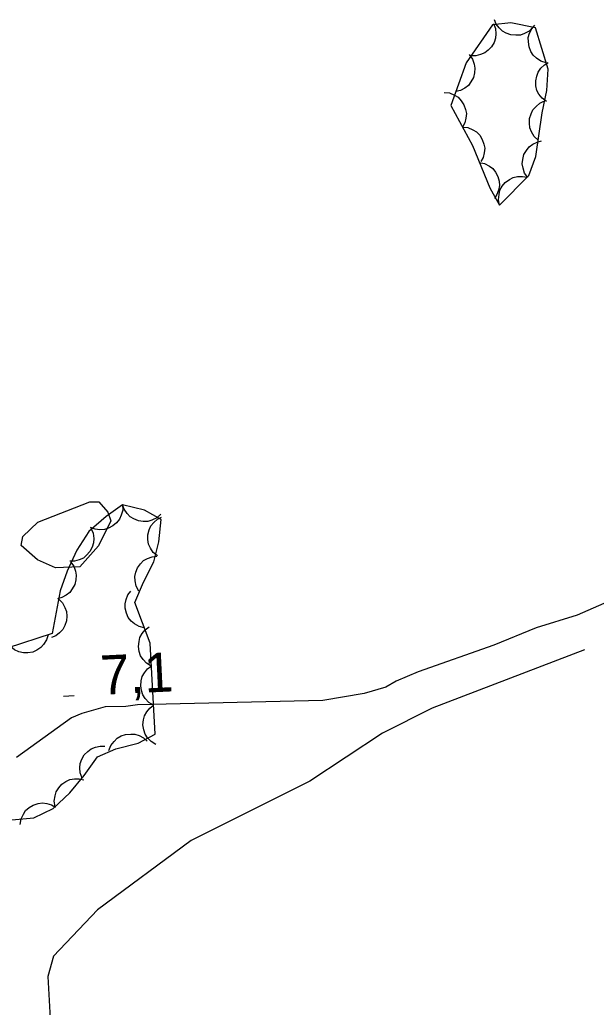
# Model space of a CAD drawing. Extents: x 336540 to 340074, y 5572036 to 5573747.
# Drawn here: x 337314.2 to 337358.4, y 5573040 to 5573115.5 of the extents above; entities that cross this region are included whole.
import ezdxf

# ---------------------------------------------------------------- set-up
doc = ezdxf.new("R2010")
doc.units = 0
for name, color, linetype in [('Niveau 2', 7, 'Continuous'), ('Niveau 3', 7, 'Continuous'), ('Niveau 44', 7, 'Continuous')]:
    doc.layers.add(name, color=color, linetype=linetype)

msp = doc.modelspace()

# ---------------------------------------------------------------- linework, layer by layer
at = {"layer": 'Niveau 2'}
for points in [[(337314.36, 5573075.34), (337314.48, 5573076.02), (337315.62, 5573077.11), (337319.61, 5573078.66), (337320.29, 5573078.68), (337320.99, 5573077.88), (337321.21, 5573077.23), (337320.27, 5573075.31), (337318.84, 5573073.71), (337316.98, 5573073.62), (337315.6, 5573074.23), (337314.36, 5573075.34)], [(337359.35, 5573071.07), (337356.9, 5573070), (337353.76, 5573069.03), (337350.53, 5573067.72), (337344.72, 5573065.67), (337343.04, 5573064.96), (337342.26, 5573064.49), (337340.59, 5573064), (337337.44, 5573063.48), (337323.26, 5573063.15), (337322.36, 5573063.02), (337320.78, 5573062.98), (337318.99, 5573062.49), (337318.21, 5573062.14), (337314, 5573059.11)], [(337357.47, 5573067.35), (337345.81, 5573062.88), (337341.99, 5573060.98), (337336.44, 5573057.31), (337327.35, 5573052.76), (337320.18, 5573047.47), (337316.82, 5573043.91), (337316.39, 5573042.35), (337316.57, 5573039.16), (337315.31, 5573034), (337313.57, 5573031.35)]]:
    msp.add_lwpolyline(points, dxfattribs=at)
at = {"layer": 'Niveau 3'}
msp.add_line((337317.6, 5573063.81), (337318.4, 5573063.85), dxfattribs=at)
at = {"layer": 'Niveau 44'}
for points in [[(337353.51, 5573114.98), (337353.22, 5573114.68), (337352.86, 5573114.49), (337352.55, 5573114.38), (337352.2, 5573114.36), (337351.83, 5573114.4), (337351.47, 5573114.53), (337351.18, 5573114.68), (337350.93, 5573114.92), (337350.71, 5573115.22), (337350.57, 5573115.55)], [(337350.96, 5573101.37), (337353.19, 5573103.64), (337353.74, 5573105.1), (337354.23, 5573108.42), (337354.59, 5573110.13), (337354.67, 5573111.77), (337353.71, 5573114.94), (337351.82, 5573115.31), (337350.41, 5573115.15), (337348.41, 5573112.26), (337347.24, 5573109), (337348.88, 5573105.92), (337350.22, 5573102.7), (337350.96, 5573101.37)], [(337350.49, 5573115.27), (337350.64, 5573114.88), (337350.67, 5573114.47), (337350.66, 5573114.14), (337350.54, 5573113.81), (337350.35, 5573113.49), (337350.09, 5573113.22), (337349.83, 5573113.01), (337349.51, 5573112.88), (337349.15, 5573112.8), (337348.79, 5573112.8)], [(337354.52, 5573112.26), (337354.12, 5573112.38), (337353.79, 5573112.61), (337353.54, 5573112.83), (337353.35, 5573113.13), (337353.22, 5573113.47), (337353.17, 5573113.85), (337353.16, 5573114.18), (337353.26, 5573114.52), (337353.43, 5573114.85), (337353.65, 5573115.13)], [(337348.63, 5573112.88), (337348.88, 5573112.54), (337349.01, 5573112.16), (337349.08, 5573111.84), (337349.05, 5573111.49), (337348.96, 5573111.13), (337348.77, 5573110.79), (337348.58, 5573110.53), (337348.3, 5573110.32), (337347.97, 5573110.15), (337347.62, 5573110.06)], [(337354.55, 5573109.29), (337354.21, 5573109.54), (337353.97, 5573109.86), (337353.82, 5573110.15), (337353.74, 5573110.5), (337353.73, 5573110.87), (337353.81, 5573111.24), (337353.91, 5573111.55), (337354.12, 5573111.84), (337354.39, 5573112.09), (337354.69, 5573112.28)], [(337346.71, 5573109.99), (337347.13, 5573109.95), (337347.5, 5573109.79), (337347.79, 5573109.62), (337348.03, 5573109.36), (337348.23, 5573109.05), (337348.35, 5573108.69), (337348.42, 5573108.37), (337348.38, 5573108.02), (337348.29, 5573107.66), (337348.12, 5573107.34)], [(337353.92, 5573106.34), (337353.62, 5573106.63), (337353.41, 5573106.98), (337353.28, 5573107.28), (337353.24, 5573107.63), (337353.26, 5573108), (337353.38, 5573108.36), (337353.51, 5573108.66), (337353.75, 5573108.92), (337354.04, 5573109.16), (337354.36, 5573109.31)], [(337348.12, 5573107.34), (337348.54, 5573107.3), (337348.91, 5573107.14), (337349.2, 5573106.97), (337349.44, 5573106.71), (337349.64, 5573106.4), (337349.76, 5573106.04), (337349.83, 5573105.72), (337349.79, 5573105.37), (337349.7, 5573105.01), (337349.53, 5573104.7)], [(337353.13, 5573103.47), (337352.88, 5573103.81), (337352.76, 5573104.2), (337352.69, 5573104.52), (337352.73, 5573104.87), (337352.83, 5573105.23), (337353.02, 5573105.56), (337353.22, 5573105.82), (337353.5, 5573106.03), (337353.83, 5573106.19), (337354.18, 5573106.28)], [(337349.41, 5573104.64), (337349.82, 5573104.56), (337350.18, 5573104.36), (337350.45, 5573104.17), (337350.66, 5573103.89), (337350.83, 5573103.56), (337350.92, 5573103.19), (337350.96, 5573102.86), (337350.89, 5573102.52), (337350.76, 5573102.17), (337350.57, 5573101.87)], [(337350.96, 5573101.37), (337350.88, 5573101.78), (337350.92, 5573102.18), (337350.99, 5573102.51), (337351.16, 5573102.81), (337351.4, 5573103.1), (337351.71, 5573103.32), (337351.99, 5573103.48), (337352.34, 5573103.56), (337352.71, 5573103.57), (337353.06, 5573103.51)], [(337311.94, 5573054.2), (337315.33, 5573054.51), (337316.79, 5573055.22), (337318.07, 5573056.41), (337319.16, 5573057.74), (337320.18, 5573059.16), (337321.6, 5573059.77), (337323.31, 5573060.2), (337324.61, 5573060.91), (337324.21, 5573067.85), (337323.05, 5573070.97), (337323.7, 5573072.53), (337324.51, 5573074.09), (337324.89, 5573075.6), (337325.07, 5573077.33), (337323.8, 5573078.03), (337322.1, 5573078.44), (337320.85, 5573077.56), (337319.53, 5573076.4), (337318.61, 5573074.97), (337317.87, 5573073.38), (337317.33, 5573071.86), (337316.72, 5573068.61), (337313.29, 5573067.49)], [(337322.11, 5573078.45), (337322.12, 5573078.03), (337322.01, 5573077.64), (337321.88, 5573077.34), (337321.65, 5573077.07), (337321.37, 5573076.83), (337321.02, 5573076.66), (337320.72, 5573076.56), (337320.36, 5573076.54), (337320, 5573076.59), (337319.66, 5573076.72)], [(337325.03, 5573077.73), (337324.72, 5573077.45), (337324.35, 5573077.28), (337324.04, 5573077.18), (337323.69, 5573077.17), (337323.32, 5573077.22), (337322.97, 5573077.37), (337322.69, 5573077.53), (337322.45, 5573077.79), (337322.24, 5573078.1), (337322.11, 5573078.44)], [(337324.78, 5573074.53), (337324.46, 5573074.8), (337324.24, 5573075.14), (337324.09, 5573075.44), (337324.04, 5573075.78), (337324.05, 5573076.15), (337324.15, 5573076.52), (337324.27, 5573076.83), (337324.49, 5573077.1), (337324.77, 5573077.34), (337325.09, 5573077.51)], [(337319.69, 5573076.65), (337319.86, 5573076.27), (337319.9, 5573075.86), (337319.89, 5573075.53), (337319.79, 5573075.2), (337319.61, 5573074.87), (337319.35, 5573074.59), (337319.11, 5573074.37), (337318.79, 5573074.23), (337318.43, 5573074.14), (337318.07, 5573074.13)], [(337318.12, 5573074.09), (337318.37, 5573073.76), (337318.51, 5573073.37), (337318.57, 5573073.05), (337318.54, 5573072.7), (337318.45, 5573072.34), (337318.26, 5573072.01), (337318.08, 5573071.74), (337317.8, 5573071.53), (337317.47, 5573071.36), (337317.12, 5573071.26)], [(337323.35, 5573071.85), (337323.15, 5573072.22), (337323.07, 5573072.62), (337323.05, 5573072.95), (337323.12, 5573073.29), (337323.26, 5573073.63), (337323.49, 5573073.94), (337323.72, 5573074.18), (337324.02, 5573074.35), (337324.37, 5573074.47), (337324.73, 5573074.52)], [(337323.77, 5573069.03), (337323.37, 5573069.13), (337323.02, 5573069.33), (337322.76, 5573069.54), (337322.55, 5573069.83), (337322.4, 5573070.16), (337322.32, 5573070.54), (337322.3, 5573070.86), (337322.38, 5573071.2), (337322.52, 5573071.55), (337322.73, 5573071.84)], [(337317.21, 5573071.24), (337317.51, 5573070.95), (337317.7, 5573070.59), (337317.82, 5573070.28), (337317.85, 5573069.93), (337317.81, 5573069.56), (337317.68, 5573069.2), (337317.53, 5573068.91), (337317.29, 5573068.65), (337316.99, 5573068.43), (337316.66, 5573068.29)], [(337316.41, 5573068.51), (337316.3, 5573068.11), (337316.07, 5573067.77), (337315.86, 5573067.52), (337315.56, 5573067.32), (337315.23, 5573067.18), (337314.85, 5573067.12), (337314.52, 5573067.11), (337314.18, 5573067.2), (337313.84, 5573067.36), (337313.56, 5573067.58)], [(337324.31, 5573066.11), (337323.95, 5573066.32), (337323.68, 5573066.62), (337323.49, 5573066.9), (337323.38, 5573067.23), (337323.33, 5573067.6), (337323.37, 5573067.98), (337323.44, 5573068.3), (337323.62, 5573068.6), (337323.85, 5573068.89), (337324.14, 5573069.1)], [(337324.48, 5573063.11), (337324.12, 5573063.33), (337323.85, 5573063.63), (337323.66, 5573063.9), (337323.55, 5573064.24), (337323.5, 5573064.6), (337323.54, 5573064.98), (337323.61, 5573065.3), (337323.79, 5573065.6), (337324.02, 5573065.89), (337324.31, 5573066.11)], [(337324.66, 5573060.12), (337324.3, 5573060.33), (337324.02, 5573060.63), (337323.83, 5573060.91), (337323.73, 5573061.24), (337323.67, 5573061.61), (337323.71, 5573061.99), (337323.78, 5573062.31), (337323.96, 5573062.61), (337324.2, 5573062.9), (337324.48, 5573063.11)], [(337321.07, 5573059.64), (337321.21, 5573060.03), (337321.46, 5573060.35), (337321.69, 5573060.59), (337322, 5573060.76), (337322.34, 5573060.88), (337322.73, 5573060.91), (337323.05, 5573060.9), (337323.39, 5573060.79), (337323.71, 5573060.61), (337323.98, 5573060.37)], [(337319.01, 5573057.53), (337318.87, 5573057.93), (337318.84, 5573058.33), (337318.87, 5573058.66), (337318.99, 5573058.99), (337319.18, 5573059.31), (337319.46, 5573059.58), (337319.71, 5573059.78), (337320.04, 5573059.91), (337320.4, 5573059.98), (337320.76, 5573059.97)], [(337316.95, 5573055.37), (337316.88, 5573055.78), (337316.94, 5573056.18), (337317.03, 5573056.5), (337317.22, 5573056.8), (337317.46, 5573057.07), (337317.78, 5573057.28), (337318.07, 5573057.43), (337318.42, 5573057.49), (337318.79, 5573057.49), (337319.14, 5573057.41)], [(337314.28, 5573054), (337314.34, 5573054.42), (337314.52, 5573054.78), (337314.69, 5573055.06), (337314.96, 5573055.29), (337315.28, 5573055.48), (337315.65, 5573055.59), (337315.97, 5573055.65), (337316.32, 5573055.6), (337316.67, 5573055.49), (337316.98, 5573055.31)]]:
    msp.add_lwpolyline(points, dxfattribs=at)

# ---------------------------------------------------------------- texts
at = {"layer": 'Niveau 3'}
msp.add_text('7,1    ', height=3, rotation=2.7712, dxfattribs=at).set_placement((337320.48, 5573063.91))

doc.saveas('drawing.dxf')
